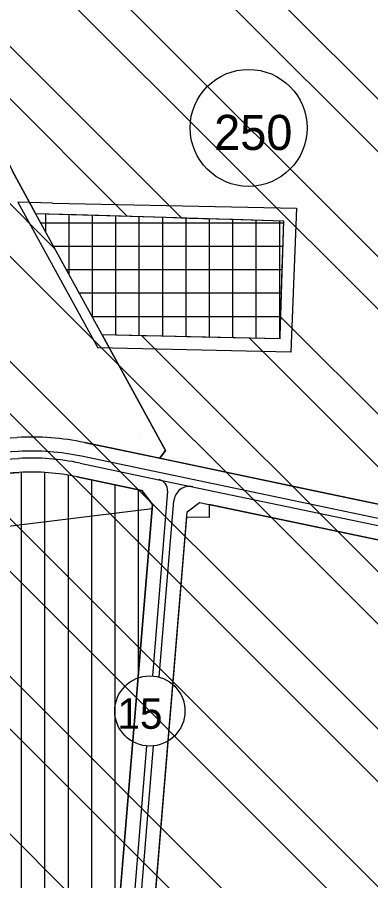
# Model space of a CAD drawing. Extents: x 409341 to 428634, y 4447481 to 4463281.
# Drawn here: x 420906.8 to 421057.8, y 4458160.3 to 4458529.4 of the extents above; entities that cross this region are included whole.
import ezdxf

# ---------------------------------------------------------------- set-up
doc = ezdxf.new("R2010")
doc.units = 0
for name, color, linetype in [('ADA', 7, 'Continuous'), ('ADAKENARI', 7, 'Continuous'), ('Default', 7, 'Continuous'), ('KALDIRIM', 7, 'Continuous'), ('KD_DAIRE', 7, 'Continuous'), ('KD_YGEN', 7, 'Continuous'), ('PL_K_TALI_IS_MRK', 7, 'Continuous'), ('PL_KON_MEV_250', 7, 'Continuous'), ('PL_KON_ONE_250', 7, 'Continuous'), ('PL_SAY_SPOR', 7, 'Continuous'), ('SM_DAIRE', 7, 'Continuous'), ('SM_TAKS', 7, 'Continuous'), ('SN_PLN_DEG', 7, 'Continuous'), ('SN_TR_SIVILASMA', 7, 'Continuous'), ('TR_KENTSELSPOR', 7, 'Continuous'), ('TR_ORTAGELISME', 7, 'Continuous'), ('TR_ORTAYOGUNKONUT', 7, 'Continuous'), ('TR_PARKALANI', 7, 'Continuous'), ('TR_TALIISMERK', 7, 'Continuous')]:
    doc.layers.add(name, color=color, linetype=linetype)

# ---------------------------------------------------------------- blocks, each defined once
blk = doc.blocks.new('POINT_DISPLAY')
at = {"layer": 'Default'}
blk.add_line((0, 0), (0, 0), dxfattribs=at)

msp = doc.modelspace()

# ---------------------------------------------------------------- linework, layer by layer
at = {"layer": 'ADA'}
for p, q in [((420914.61, 4458445.59), (420970.24, 4458443.92)), ((420943.04, 4458393.72), (420914.61, 4458445.59)), ((420970.24, 4458443.92), (421020.52, 4458442.41)), ((421020.52, 4458442.41), (421019, 4458393.13)), ((421018.97, 4458391.91), (420943.04, 4458393.72)), ((421019, 4458393.13), (421018.97, 4458391.91)), ((420744.27, 4458292.48), (420964.39, 4458319.42))]:
    msp.add_line(p, q, dxfattribs=at)
at = {"layer": 'ADAKENARI'}
for p, q in [((420946.45, 4458345.32), (420935.43, 4458347.63)), ((421031.06, 4458327.58), (420946.45, 4458345.32)), ((420847.49, 4458331.49), (420907.59, 4458334.83)), ((420932.35, 4458332.95), (420960.06, 4458327.14)), ((420960.06, 4458327.14), (420964.54, 4458321.14)), ((421088.37, 4458315.57), (421031.06, 4458327.58)), ((420964.39, 4458319.42), (420945.51, 4458091.58)), ((420964.54, 4458321.14), (420964.39, 4458319.42)), ((420979.33, 4458318.03), (420984.64, 4458321.99)), ((420984.64, 4458321.99), (421085.29, 4458300.89)), ((420960.46, 4458090.34), (420979.33, 4458318.03))]:
    msp.add_line(p, q, dxfattribs=at)
for radius in [110, 95]:
    msp.add_arc((420912.86, 4458239.98), radius, 78.1579, 93.1798, dxfattribs=at)
at = {"layer": 'KALDIRIM'}
for p, q in [((420907.09, 4458343.82), (420847.49, 4458340.5)), ((421029.83, 4458321.71), (420934.2, 4458341.76)), ((420847.49, 4458337.5), (420907.26, 4458340.82)), ((420933.58, 4458338.83), (420967.32, 4458331.75)), ((420967.32, 4458331.75), (421086.52, 4458306.76)), ((420971.03, 4458326.78), (420964.48, 4458247.81)), ((420967.45, 4458247.3), (420973.7, 4458322.68)), ((421087.13, 4458309.69), (421029.83, 4458321.71)), ((420962, 4458217.92), (420951.49, 4458091.08)), ((420954.48, 4458090.83), (420965.01, 4458217.94))]:
    msp.add_line(p, q, dxfattribs=at)
for centre, radius, start, end in [((420912.86, 4458239.98), 104, 78.1579, 93.1798), ((420912.86, 4458239.98), 101, 78.1579, 93.1798), ((420966.36, 4458327.17), 4.68, 355.2626, 78.1579), ((420980.41, 4458322.12), 6.74, 78.1579, 175.2626)]:
    msp.add_arc(centre, radius, start, end, dxfattribs=at)
at = {"layer": 'KD_DAIRE'}
msp.add_circle((420963.42, 4458232.85), 15, dxfattribs=at)
at = {"layer": 'PL_K_TALI_IS_MRK'}
for p, q in [((420943.04, 4458393.72), (420914.61, 4458445.59)), ((420914.61, 4458445.59), (420932, 4458445.07)), ((420932, 4458445.07), (420970.24, 4458443.92)), ((420970.24, 4458443.92), (420980.24, 4458443.62)), ((420980.24, 4458443.62), (420997.7, 4458443.1)), ((420997.7, 4458443.1), (420998.87, 4458443.06)), ((420998.87, 4458443.06), (421020.52, 4458442.41)), ((421020.52, 4458442.41), (421019.71, 4458417.58)), ((421019.71, 4458417.58), (421019.55, 4458412.17)), ((421019.55, 4458412.17), (421019.36, 4458406.35)), ((421019.36, 4458406.35), (421019.27, 4458403.72)), ((421019.27, 4458403.72), (421019, 4458393.13)), ((420960.37, 4458393.3), (420943.04, 4458393.72)), ((420969.08, 4458393.1), (420960.37, 4458393.3)), ((420979.02, 4458392.86), (420969.08, 4458393.1)), ((421018.97, 4458391.91), (420979.02, 4458392.86)), ((421019, 4458393.13), (421018.97, 4458391.91))]:
    msp.add_line(p, q, dxfattribs=at)
at = {"layer": 'PL_KON_MEV_250'}
for points in [[(420907.59, 4458334.83), (420847.49, 4458331.49), (420834.36, 4458330.76)], [(420945.51, 4458091.58), (420964.39, 4458319.42), (420964.54, 4458321.14), (420960.06, 4458327.14), (420932.35, 4458332.95)], [(421085.29, 4458300.89), (420988.83, 4458321.11), (420988.83, 4458315.56), (420979.14, 4458315.7), (420960.46, 4458090.34)]]:
    msp.add_lwpolyline(points, dxfattribs=at)
msp.add_arc((420912.86, 4458239.98), 95, 78.1579, 93.1798, dxfattribs=at)
at = {"layer": 'PL_KON_ONE_250'}
for p, q in [((420914.61, 4458445.59), (420932, 4458445.07)), ((420932, 4458445.07), (420970.24, 4458443.92)), ((420970.24, 4458443.92), (420983.08, 4458443.53)), ((421020.52, 4458442.41), (421019, 4458393.13)), ((420960.37, 4458393.3), (420943.04, 4458393.72))]:
    msp.add_line(p, q, dxfattribs=at)
for points in [[(421199.4, 4458546.37), (421071.94, 4458546.37), (420879.6, 4458554.52), (420872.41, 4458553.58), (420857.15, 4458548.81), (420864.13, 4458545.82), (420899.22, 4458474.76), (420904.7, 4458463.67), (420914.61, 4458445.59)], [(420983.08, 4458443.53), (420997.7, 4458443.1), (420998.87, 4458443.06), (421020.52, 4458442.41)], [(420943.04, 4458393.72), (420970.15, 4458344.23), (420967.66, 4458340.88), (421031.06, 4458327.58), (421088.37, 4458315.57)], [(421019, 4458393.13), (421018.97, 4458391.91), (420979.02, 4458392.86), (420969.08, 4458393.1), (420960.37, 4458393.3)]]:
    msp.add_lwpolyline(points, dxfattribs=at)
at = {"layer": 'PL_SAY_SPOR'}
for p, q in [((420833.53, 4458345.74), (420906.76, 4458349.81)), ((420935.43, 4458347.63), (420967.66, 4458340.88)), ((420967.66, 4458340.88), (420970.15, 4458344.23))]:
    msp.add_line(p, q, dxfattribs=at)
msp.add_lwpolyline([(420970.15, 4458344.23), (420943.04, 4458393.72), (420914.61, 4458445.59), (420904.7, 4458463.67)], dxfattribs=at)
msp.add_arc((420912.86, 4458239.98), 110, 78.1579, 93.1798, dxfattribs=at)
at = {"layer": 'SM_DAIRE'}
msp.add_circle((421005.62, 4458482.16), 25, dxfattribs=at)
at = {"layer": 'SN_PLN_DEG'}
for p, q in [((420921.87, 4458449.93), (420907.01, 4458450.46)), ((420907.01, 4458450.46), (420941.14, 4458388.12)), ((420921.87, 4458449.93), (421026.11, 4458447.9)), ((421026.11, 4458447.9), (421023.6, 4458386.33)), ((421023.6, 4458386.33), (420941.14, 4458388.12))]:
    msp.add_line(p, q, dxfattribs=at)
at = {"layer": 'SN_TR_SIVILASMA'}
for p, q in [((421299.44, 4458166.1), (420879.12, 4458586.42)), ((421299.67, 4458188.32), (420901.57, 4458586.42)), ((421300.13, 4458232.76), (420946.47, 4458586.42)), ((421300.13, 4458232.76), (420946.47, 4458586.42)), ((421300.37, 4458254.98), (420968.92, 4458586.42)), ((421300.37, 4458254.98), (420968.92, 4458586.42)), ((420976.93, 4458443.72), (420847.49, 4458573.15)), ((420953.78, 4458444.41), (420847.49, 4458550.7)), ((420922.98, 4458430.31), (420847.49, 4458505.8)), ((421298.05, 4458032.79), (420847.49, 4458483.35)), ((421297.58, 4457988.35), (420847.49, 4458438.45)), ((421297.35, 4457966.14), (420847.49, 4458416)), ((421298.97, 4458121.67), (421019.26, 4458401.39)), ((421298.28, 4458055.01), (420959.98, 4458393.31)), ((421298.74, 4458099.45), (421005.98, 4458392.22)), ((421296.89, 4457921.7), (420847.49, 4458371.1)), ((421296.66, 4457899.48), (420847.49, 4458348.64)), ((421296.19, 4457855.04), (420847.49, 4458303.74)), ((421295.96, 4457832.82), (420847.49, 4458281.29)), ((421295.5, 4457788.39), (420847.49, 4458236.39))]:
    msp.add_line(p, q, dxfattribs=at)
at = {"layer": 'TR_ORTAGELISME'}
for p, q in [((420914.61, 4458445.59), (420932, 4458445.07)), ((420932, 4458445.07), (420970.24, 4458443.92)), ((420970.24, 4458443.92), (420983.08, 4458443.53)), ((421020.52, 4458442.41), (421019, 4458393.13)), ((420960.37, 4458393.3), (420943.04, 4458393.72))]:
    msp.add_line(p, q, dxfattribs=at)
for points in [[(421199.4, 4458546.37), (421071.94, 4458546.37), (420879.6, 4458554.52), (420872.41, 4458553.58), (420857.15, 4458548.81), (420864.13, 4458545.82), (420899.22, 4458474.76), (420904.7, 4458463.67), (420914.61, 4458445.59)], [(420983.08, 4458443.53), (420997.7, 4458443.1), (420998.87, 4458443.06), (421020.52, 4458442.41)], [(420943.04, 4458393.72), (420970.15, 4458344.23), (420967.66, 4458340.88)], [(421019, 4458393.13), (421018.97, 4458391.91), (420979.02, 4458392.86), (420969.08, 4458393.1), (420960.37, 4458393.3)], [(420967.66, 4458340.88), (421031.06, 4458327.58), (421088.37, 4458315.57)]]:
    msp.add_lwpolyline(points, dxfattribs=at)
msp.add_circle((421005.62, 4458482.16), 25, dxfattribs=at)
at = {"layer": 'TR_ORTAYOGUNKONUT'}
for p, q in [((420908.59, 4457779.61), (420908.59, 4458334.88)), ((420918.59, 4457779.51), (420918.59, 4458334.8)), ((420928.59, 4457779.4), (420928.59, 4458333.66)), ((420938.59, 4457779.29), (420938.59, 4458331.65)), ((420948.59, 4458128.72), (420948.59, 4458329.55)), ((420958.59, 4458249.39), (420958.59, 4458327.45))]:
    msp.add_line(p, q, dxfattribs=at)
for points in [[(420907.59, 4458334.83), (420847.49, 4458331.49), (420834.36, 4458330.76)], [(420945.51, 4458091.58), (420964.39, 4458319.42), (420964.54, 4458321.14), (420960.06, 4458327.14), (420932.35, 4458332.95)], [(421085.29, 4458300.89), (420988.83, 4458321.11), (420988.83, 4458315.56), (420979.14, 4458315.7), (420960.46, 4458090.34)]]:
    msp.add_lwpolyline(points, dxfattribs=at)
msp.add_arc((420912.86, 4458239.98), 95, 78.1579, 93.1798, dxfattribs=at)
at = {"layer": 'TR_TALIISMERK'}
for p, q in [((420918.91, 4458437.74), (420918.91, 4458445.46)), ((420928.91, 4458419.5), (420928.91, 4458445.16)), ((420938.91, 4458401.25), (420938.91, 4458444.86)), ((420948.91, 4458393.58), (420948.91, 4458444.56)), ((420916.8, 4458441.58), (421020.5, 4458441.58)), ((420958.91, 4458393.34), (420958.91, 4458444.26)), ((420968.91, 4458393.1), (420968.91, 4458443.96)), ((420978.91, 4458392.86), (420978.91, 4458443.66)), ((420988.91, 4458392.62), (420988.91, 4458443.36)), ((420998.91, 4458392.38), (420998.91, 4458443.06)), ((421008.91, 4458392.15), (421008.91, 4458442.76)), ((421018.91, 4458391.91), (421018.91, 4458442.45)), ((420922.28, 4458431.58), (421020.17, 4458431.58)), ((420927.76, 4458421.58), (421019.84, 4458421.58)), ((420933.24, 4458411.58), (421019.53, 4458411.58)), ((420938.72, 4458401.58), (421019.22, 4458401.58))]:
    msp.add_line(p, q, dxfattribs=at)

# ---------------------------------------------------------------- block references
at = {"layer": 'TR_KENTSELSPOR', "xscale": 0.1, "yscale": 0.10000000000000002}
for p in [(420919.2, 4458350.55), (420919.2, 4458350.55), (420919.2, 4458350.55), (420919.2, 4458350.55), (420959.2, 4458350.55), (420959.2, 4458350.55), (420959.2, 4458350.55), (420959.2, 4458350.55)]:
    msp.add_blockref('POINT_DISPLAY', p, dxfattribs=at)
at = {"layer": 'TR_PARKALANI', "xscale": 0.1, "yscale": 0.10000000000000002}
msp.add_blockref('POINT_DISPLAY', (420906.79, 4458452.33), dxfattribs=at)
msp.add_blockref('POINT_DISPLAY', (420906.79, 4458452.33), dxfattribs=at)

# ---------------------------------------------------------------- texts
at = {"layer": 'KD_YGEN'}
msp.add_text('15', height=13, dxfattribs=at).set_placement((420949.5, 4458225.23))
at = {"layer": 'SM_TAKS'}
msp.add_text('250', height=15, dxfattribs=at).set_placement((420990.88, 4458472.72))

doc.saveas('drawing.dxf')
